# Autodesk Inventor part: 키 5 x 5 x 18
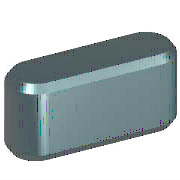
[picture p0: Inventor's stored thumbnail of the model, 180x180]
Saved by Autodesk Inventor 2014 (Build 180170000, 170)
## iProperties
IsCustomPart: 1
Created: 2012-02
Part Number: 키 5 x 5 x 18
Material: 강철, 연강
Description: 키 및 해당 키홈
Document SubType Name: Modeling
Standard: KS B 1311
Designer: mduedu
Standards Organization: KS
Language: ko-KR
Size Designation: 5 x 5 x 18
Categories: <MemberInstance><Categories><Category DisplayName="샤프트 부품" InternalName="7f7aeb1f-a693-4053-b835-cee3144e0d98" Mnemonic="SHFT"><Category DisplayName="키" Interna
Density: 7.86 g/cm^3
Appearance: 노란색
Mass: 3.27476 g
Surface Area: 3.57848 cm^2
Volume: 0.416636 cm^3
Author: mduedu
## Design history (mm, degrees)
workplane "Work Plane1"
workplane "Work Plane2"
sketch "스케치1"
  geometry: L1 (2.5, 2.5)-(15.5, 2.5); L2 (15.5, -2.5)-(2.5, -2.5); L3 (0, 9.4)-(0, -7.4) reference; L4 (-5, 0)-(30, 0) reference; L5 (18, 0)-(18, 7); A1 r 2.5 centre (2.5, 0) between (2.5, 2.5) and (2.5, -2.5); A2 r 2.5 centre (15.5, 0) between (15.5, -2.5) and (15.5, 2.5)
  constraints: 6 end point, 5 point on circle, 4 tangent, 3 point on line, 2 centre point, 1 horizontal, 1 parallel, 1 perpendicular
  dimensions: "d0" = 2.5 radius of A1 (= 0.5 x PB); "d13" = 2.5 radius of A2 (= 0.5 x PB); "d14" = 18 distance between parallel lines of L5 L3 (= NLG)
extrude "본체1" new body sketch "스케치1" taper "d3" = 0 deg; stored distance "d4" = 10
workplane "Work Plane3"
body "Solid1"
chamfer "모따기1" distance "d8" = 0.4 (= PHH); stored, may be unused: second distance "d9" = 0.4 (= PHH), angle "d15" = 45 deg
other parameters: "d1" = -3 (= -PNT), "d2" = 2 (= PH - PNT), "NLG" = 18 [user parameter; used in 3 equation terms], "PB" = 5 [user parameter; used in 2 equation terms], "PNT" = 3 [user parameter; used in 2 equation terms], "PH" = 5 [user parameter; used in 1 equation term], "PHH" = 0.4 [user parameter; used in 2 equation terms], "d10" = 0, "d16" = 0, "d17" = 0, "d18" = 0, "WDMIN" = 12 [user parameter], "PLB2" = 18 (= NLG) [user parameter], "WDMAX" = 17 [user parameter], "PLB1" = 18 (= NLG) [user parameter], "RR" = 0.16 [user parameter], "PUEB" = 2.3 [user parameter]
